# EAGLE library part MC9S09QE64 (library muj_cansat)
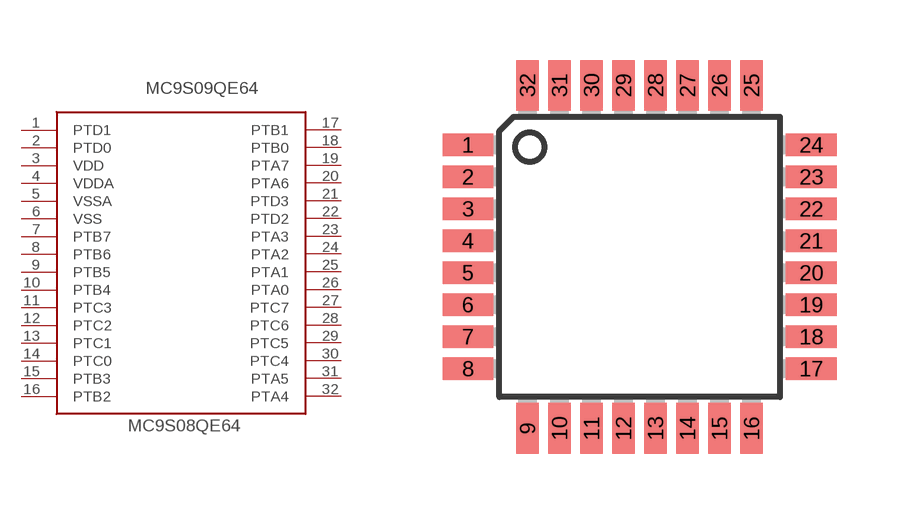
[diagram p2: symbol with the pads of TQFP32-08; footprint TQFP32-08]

Designator prefix E

## MC9S09QE64  [TQFP32-08]
1  PTD1
2  PTD0
3  VDD
4  VDDA
5  VSSA
6  VSS
7  PTB7
8  PTB6
9  PTB5
10  PTB4
11  PTC3
12  PTC2
13  PTC1
14  PTC0
15  PTB3
16  PTB2
17  PTB1
18  PTB0
19  PTA7
20  PTA6
21  PTD3
22  PTD2
23  PTA3
24  PTA2
25  PTA1
26  PTA0
27  PTC7
28  PTC6
29  PTC5
30  PTC4
31  PTA5
32  PTA4

## Footprint TQFP32-08 (pad centres in mm)
Thin Plasic Quad Flat Package Grid 0.8 mm
smd 1.27 x 0.559: 1 -4.293,2.8; 2 -4.293,2; 3 -4.293,1.2; 4 -4.293,0.4; 5 -4.293,-0.4; 6 -4.293,-1.2; 7 -4.293,-2; 8 -4.293,-2.8; 17 4.293,-2.8; 18 4.293,-2; 19 4.293,-1.2; 20 4.293,-0.4; 21 4.293,0.4; 22 4.293,1.2; 23 4.293,2; 24 4.293,2.8
smd 0.559 x 1.27: 9 -2.8,-4.293; 10 -2,-4.293; 11 -1.2,-4.293; 12 -0.4,-4.293; 13 0.4,-4.293; 14 1.2,-4.293; 15 2,-4.293; 16 2.8,-4.293; 25 2.8,4.293; 26 2,4.293; 27 1.2,4.293; 28 0.4,4.293; 29 -0.4,4.293; 30 -1.2,4.293; 31 -2,4.293; 32 -2.8,4.293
